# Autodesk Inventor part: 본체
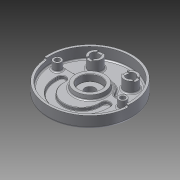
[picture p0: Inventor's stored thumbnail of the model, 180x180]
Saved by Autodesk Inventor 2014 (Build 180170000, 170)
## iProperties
Created: 2015-05
Part Number: 본체
Material: 알루미늄 6061
Document SubType Name: Modeling
Designer: USER
Density: 2.71 g/cm^3
Appearance: 알루미늄 - 평지
Mass: 1082.54 g
Surface Area: 1039.75 cm^2
Volume: 399.463 cm^3
Author: USER
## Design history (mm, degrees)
sketch "스케치1"
  geometry: C1 r 95 at (0, 0); 1 further point
  constraints: 1 centre point, 1 coincident
  dimensions: "d0" = 190 diameter of C1
extrude "돌출1" new body sketch "스케치1" distance "d1" = 32; taper "d2" = 0 deg
sketch "스케치2"
  geometry: C1 r 95 at (0, 0) reference; C2 r 90 at (0, 0)
  constraints: 1 centre point, 1 coincident
  dimensions: "d3" = 180 diameter of C2
extrude "돌출2" cut sketch "스케치2" distance "d4" = 25; taper "d5" = 0 deg
sketch "스케치3"
  geometry: C1 r 95 at (0, 0) reference; C2 r 25 at (0, 0)
  constraints: 1 centre point, 1 coincident
  dimensions: "d6" = 50 diameter of C2
extrude "돌출3" join sketch "스케치3" distance "d7" = 12; taper "d8" = -15 deg
sketch "스케치4"
  geometry: L1 (0, 0)-(95, 0); L2 (0, 0)-(94.638, -8.28); L3 (0, 0)-(-94.638, -8.28); C1 r 90 at (0, 0) reference; A1 r 95 centre (0, 0) between (95, 0) and (94.638, -8.28) reference
  constraints: 6 end point, 3 point on circle, 1 horizontal
  dimensions: "d9" = 5 deg angle of L2 L1; "d10" = 170 deg angle of L3 L2
extrude "돌출4" cut sketch "스케치4" distance "d11" = 5; taper "d12" = 0 deg
sketch "스케치5"
  geometry: L1 (-89.196, 12)-(89.196, 12); C1 r 90 at (0, 0) reference; C2 r 42 at (0, 0); A1 r 90 centre (0, 0) between (-89.196, 12) and (89.196, 12) reference
  constraints: 2 end point, 2 point on circle, 1 centre point, 1 coincident, 1 horizontal
  dimensions: "d13" = 84 diameter of C2; "d14" = 12 distance from line of L1 C1.centre
extrude "돌출5" join sketch "스케치5" distance "d15" = 7; taper "d16" = 0 deg
sketch "스케치6"
  geometry: C1 r 35 at (0, 0); A1 r 42 centre (0, 0) between (40.249, 12) and (-40.249, 12) reference
  constraints: 1 centre point, 1 coincident
  dimensions: "d17" = 70 diameter of C1
extrude "돌출6" join sketch "스케치6" distance "d18" = 10; taper "d19" = -10 deg
hole "구멍1" diameter "d22" = 23; stored, may be unused: countersink angle "d26" = 90 deg, drill point angle "d28" = 118 deg; dims "d20" = 10, "d21" = 10, "d23" = 6, "d24" = 50, "d25" = 15, "d27" = 8
sketch "스케치7"
  geometry: C1 r 25 at (0, 0) reference; C2 r 9 at (-74, 0); 1 further point
  constraints: 1 centre point, 1 coincident, 1 horizontal alignment
  dimensions: "d29" = 74 distance of C1.centre point (-74, 0); "d30" = 18 diameter of C2
extrude "돌출7" join sketch "스케치7" distance "d31" = 32; taper "d32" = 0 deg
hole "구멍2" sketch "스케치7" diameter "d33" = 11; stored, may be unused: countersink angle "d37" = 90 deg, drill point angle "d39" = 118 deg; dims "d34" = 6, "d35" = 18, "d36" = 11, "d38" = 8
sketch "스케치8"
  geometry: C1 r 25 at (0, 0) reference; C2 r 15 at (-40, 52); 1 further point
  constraints: 1 centre point, 1 coincident
  dimensions: "d40" = 52 vertical distance of C1.centre point (-40, 52); "d41" = 40 horizontal distance of C1.centre point (-40, 52); "d42" = 30 diameter of C2
extrude "돌출8" join sketch "스케치8" distance "d43" = 32; taper "d44" = 0 deg
hole "구멍3" sketch "스케치8" diameter "d45" = 20; stored, may be unused: countersink angle "d49" = 90 deg, drill point angle "d51" = 118 deg; dims "d46" = 6, "d47" = 18, "d48" = 11, "d50" = 8
sketch "스케치9"
  geometry: L1 (-15, -6)-(15, -6); L2 (15, -6)-(15, 6); L3 (15, 6)-(-15, 6); L4 (-15, 6)-(-15, -6); L5 (-15, -6)-(15, 6); L6 (15, -6)-(-15, 6); C1 r 15 at (0, 0) reference; 1 further point
  constraints: 12 end point, 2 midpoint, 2 parallel, 1 horizontal, 1 perpendicular, 1 tangent
  dimensions: "d52" = 12 distance between parallel lines of L1 L3
extrude "돌출9" cut sketch "스케치9" distance "d53" = 3; taper "d54" = 0 deg
sketch "스케치10"
  geometry: L1 (-6, -15)-(6, -15); L2 (6, -15)-(6, 15); L3 (6, 15)-(-6, 15); L4 (-6, 15)-(-6, -15); L5 (-6, -15)-(6, 15); L6 (6, -15)-(-6, 15); C1 r 15 at (0, 0) reference; 1 further point
  constraints: 12 end point, 2 midpoint, 2 parallel, 1 horizontal, 1 perpendicular, 1 tangent
  dimensions: "d55" = 12 distance of L3.end L2.end
extrude "돌출10" cut sketch "스케치10" distance "d56" = 3; taper "d57" = 0 deg
sketch "스케치11"
  geometry: L1 (-40.249, 12)-(-89.196, 12) reference; L2 (89.196, 12)-(40.249, 12) reference; L3 (-41, -19)-(-59, -19); L4 (41, -19)-(59, -19); L5 (-50, -19)-(-50, -14); L6 (50, -19)-(50, -14); L7 (-41, -19)-(-41, -14); L8 (-59, -14)-(-59, -19); L9 (59, -19)-(59, -14); L10 (41, -19)-(41, -14); A1 r 35 centre (0, 0) between (34.911, 2.5) and (-34.911, 2.5) reference; A2 r 41 centre (0, -19) between (-41, -19) and (41, -19); A3 r 59 centre (0, -19) between (-59, -19) and (59, -19); A4 r 41 centre (0, -19) between (34.911, 2.5) and (26.833, 12); A5 r 41 centre (0, -19) between (-26.833, 12) and (-34.911, 2.5); A6 r 50 centre (0, -19) between (-50, -19) and (50, -19); A7 r 50 centre (0, -19) between (25.426, 24.053) and (-25.426, 24.053); A8 r 9 centre (-50, -14) between (-41, -14) and (-59, -14); A9 r 9 centre (50, -14) between (59, -14) and (41, -14); 2 further points
  constraints: 23 point on circle, 16 end point, 8 centre point, 6 tangent, 4 coincident, 3 point on line, 2 equal length, 2 midpoint, 2 vertical alignment, 1 collinear, 1 perpendicular
  dimensions: "d65" = 59 radius of A3; "d66" = 41 radius of A2; "d71" = 50 radius of A6; "d74" = 19 vertical distance of A6.end A1.centre; "d75" = 5 distance of L5.start L5.end; "d76" = 5 distance of L6.start L6.end; "d77" = 18 diameter of A8; "d78" = 18 diameter of A9
extrude "돌출11" cut sketch "스케치11" distance "d79" = 7; taper "d80" = 0 deg
sketch "스케치12"
  geometry: L1 (0, 0)-(72, 0); L2 (-36.062, -36.062)-(-50.912, -50.912); L3 (36.062, -36.062)-(50.912, -50.912); L4 (0, 0)-(0, -81.693); L5 (-36.062, -36.062)-(0, 0); L6 (36.062, -36.062)-(0, 0); C1 r 95 at (0, 0) reference; A1 r 51 centre (0, 0) between (-36.062, -36.062) and (36.062, -36.062); A2 r 72 centre (0, 0) between (-50.912, -50.912) and (50.912, -50.912)
  constraints: 12 end point, 4 point on circle, 2 centre point, 2 coincident, 2 perpendicular, 1 horizontal, 1 other
  dimensions: "d85" = 72 radius of A2; "d88" = 51 radius of A1; "d89" = 90 deg angle of L3 L2
extrude "돌출12" join sketch "스케치12" distance "d90" = 5; taper "d91" = 0 deg
fillet "모깎기1" dims "d95" = 5
fillet "모깎기2" dims "d96" = 5, "d97" = 3
sketch "스케치15"
  geometry: C1 r 68 at (0, 0); A1 r 67 centre (0, 0) between (-43.709, -50.78) and (43.709, -50.78) reference
  constraints: 1 centre point, 1 coincident, 1 other
  dimensions: "d98" = 136 diameter of C1
feature "엠보싱2" sketch "스케치15" dims "d0" = 190, "d99" = 0.5, "d100" = 0
fillet "모깎기3" dims "d101" = 5
fillet "모깎기4" dims "d102" = 10
fillet "모깎기5" dims "d103" = 3
fillet "모깎기6" dims "d104" = 1
chamfer "모따기1" distance "d105" = 1; stored, may be unused: second distance "d106" = 2, angle "d107" = 45 deg
chamfer "모따기2" distance "d108" = 1; stored, may be unused: second distance "d109" = 2, angle "d110" = 45 deg
fillet "모깎기7" dims "d111" = 3
fillet "모깎기8" dims "d112" = 3
fillet "모깎기9" dims "d113" = 3
fillet "모깎기10" dims "d114" = 0.3
fillet "모깎기11" dims "d115" = 3
node "솔리드1"
mirror "대칭1"
mirror "대칭2"
node "투영된 루프1"
other parameters: "d59" = 118, "d60" = 82, "d81" = 144, "d83" = 45 deg, "d84" = 90 deg
